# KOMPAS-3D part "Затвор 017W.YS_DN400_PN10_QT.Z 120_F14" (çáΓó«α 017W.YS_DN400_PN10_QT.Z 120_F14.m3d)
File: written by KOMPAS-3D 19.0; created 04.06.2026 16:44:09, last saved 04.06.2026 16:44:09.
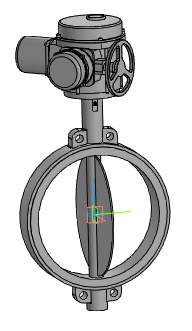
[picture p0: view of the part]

Document properties: Автор: Энергия; Полное имя файла: ..\..\..\3d для проектировщиков\017W разные\x.x Тип 017W.Y(S) Затвор дисковый поворотный межфланцевый\Затвор 017W.Y(S)_DN32-DN450_QT.Z\Затвор 017W.YS_DN400_PN10_QT.Z 120_F14.a3d

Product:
- Part/product: Затвор 017W.YS_DN400_PN10_QT.Z 120_F14
    Масса: 128.365

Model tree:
1. Операция без истории:1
